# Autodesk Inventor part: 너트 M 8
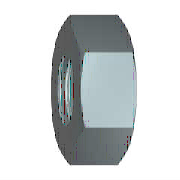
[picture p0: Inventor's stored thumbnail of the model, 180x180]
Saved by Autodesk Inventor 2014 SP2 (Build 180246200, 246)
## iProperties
IsCustomPart: 1
Created: 2012-02
Part Number: 너트 M 8
Material: 강철, 연강
Description: 6각 너트 및 6각 가는 너트
Document SubType Name: Modeling
Standard: KS B 1012
Designer: mduedu
Standards Organization: KS
Language: ko-KR
Size Designation: M 8
Categories: <MemberInstance><Categories><Category DisplayName="조임쇠" InternalName="e4da775c-781d-43d5-af7c-5136215cf5a6" Mnemonic="FSTN"><Category DisplayName="너트" InternalN
Density: 1 g/cm^3
Appearance: 강철
Author: mduedu
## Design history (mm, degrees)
sketch "스케치1"
  geometry: L1 (-7.506, 0)-(-3.753, 6.5); L2 (-3.753, 6.5)-(3.753, 6.5); L3 (3.753, 6.5)-(7.506, 0); L4 (7.506, 0)-(3.753, -6.5); L5 (3.753, -6.5)-(-3.753, -6.5); L6 (-3.753, -6.5)-(-7.506, 0); 2 further points
  constraints: 12 end point, 1 coincident, 1 horizontal, 11 other
  dimensions: "d0" = 15.01111 distance of L3.end L1.start (= 1.1547 x SW)
extrude "본체" new body sketch "스케치1" distance "d1" = 5 (= KOH); taper "d2" = 0 deg
sketch "스케치2"
  geometry: L1 (0, 3.753)-(0, 7.506) reference; L2 (0, 7.506)-(5, 7.506) reference; L3 (5, 3.753)-(5, 7.506) reference; L4 (-1, 0)-(6, 0) reference; L5 (0.581, 7.506)-(0, 6.5); L6 (4.419, 7.506)-(5, 6.5)
  constraints: 4 end point, 4 point on line
  dimensions: "d3" = 30 deg angle of L1 L5 (= ANG1); "d4" = 30 deg angle of L3 L6 (= ANG2); "d5" = 13 diameter of L5.end L4 (= SW0); "d6" = 13 diameter of L6.end L4 (= SW01)
revolve "모따기1" sketch "스케치2" stored, may be unused: angle "d7" = 90 deg
sketch "스케치3"
  geometry: A1 r 6.5 centre (0, 0) between (-3.25, -5.629) and (3.25, -5.629) reference; 1 further point
  constraints: 1 coincident
hole "스레드" sketch "스케치3" at (0, 0) diameter "d25" = 6.647; stored, may be unused: countersink angle "d29" = 82 deg, drill point angle "d31" = 118 deg; dims "d26" = 6, "d27" = 4, "d28" = 2, "d30" = 8
workaxis "Work Axis1"
workplane "Work Plane1"
body "Solid1"
chamfer "모따기2" distance "d8" = 0.67658 (= -0.5 x GD1 + 0.5 x NND); stored, may be unused: angle "d9" = 30 deg, second distance "d40" = 0.67658 (= -0.5 x GD1 + 0.5 x NND)
chamfer "모따기3" distance "d10" = 0.67658 (= -0.5 x GD1 + 0.5 x NND); stored, may be unused: angle "d11" = 30 deg, second distance "d41" = 0.67658 (= -0.5 x GD1 + 0.5 x NND)
other parameters: "ANG1" = 30 deg [user parameter; used in 1 equation term], "ANG2" = 30 deg [user parameter; used in 1 equation term], "NND" = 8 [user parameter; used in 4 equation terms], "KOH" = 5 [user parameter; used in 1 equation term], "SW" = 13 [user parameter; used in 4 equation terms], "SW0" = 13 (= SW) [user parameter; used in 1 equation term], "SW01" = 13 (= SW) [user parameter; used in 1 equation term], "GD1" = 6.64684 (computed from THREADDIA, PTC, TOA) [user parameter; used in 4 equation terms], "d13" = 0, "d14" = 0, "d39" = 0, "d42" = 0, "GUL" = 0.67658 (= 0.541266 x PTC) [user parameter], "TPU" = 8 (computed from PTC) [user parameter], "THREADDIA" = 8 [user parameter; used in 1 equation term], "TOA" = 30 deg [user parameter; used in 1 equation term], "PTC" = 1.25 [user parameter; used in 4 equation terms], "E0" = 15.015 (= 1.155 x SW) [user parameter], "GAL" = 0.67658 (= 0.541266 x PTC) [user parameter]
